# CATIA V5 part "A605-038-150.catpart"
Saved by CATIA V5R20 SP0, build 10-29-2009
Part number: A605-038-150
Source: Unknown
Property "A": "0.000"
Property "ARTICLENO": "A605-038-150"
Property "BOMINFO": "A605-038-150"
Property "CODE": "A605-038-150"
Property "D": "9.000"
Property "FORM": "B"
Property "L": "150.000"
Property "L1": "60.000"
Property "LINA": "A605-038-150"
Property "NB": "A605-038-150"
Property "NBSYN": "$CODE."
Property "NN": "A605"
Property "NT": "Wear Plates, self-lubricating"
Property "SCREW": "3*M8X16"
Property "SUPPLIER": "CF"
Property "W": "38.000"
Bounding box of the stored display mesh (mm): x -38 to 0, y 0 to 5, z -150 to 0
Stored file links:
  C:\Users\Utente\Desktop\3D files A605\A605-038-150.catpart
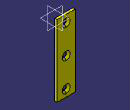
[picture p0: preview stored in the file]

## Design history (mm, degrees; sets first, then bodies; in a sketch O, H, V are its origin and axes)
Body1 "Geometry.1" (main body)
  Solid1 "A605-038-150.catpart": solid without history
